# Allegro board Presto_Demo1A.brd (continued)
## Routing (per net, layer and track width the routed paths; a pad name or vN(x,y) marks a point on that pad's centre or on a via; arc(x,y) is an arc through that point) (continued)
DDR_DQ26: length 19.8
  TOP w0.102: U2.L4 v1(54.25,93.15) ; U13.D7 v1(41.5,90.3)
  INNER1 w0.102: v1(41.5,90.3) 42.06,90.86 42.61,90.86 43.36,91.61 43.9,91.61 44,91.72 44,91.82 44.1,91.92 44.31,91.92 44.41,91.82 44.41,91.72 44.51,91.61 44.72,91.61 44.82,91.72 44.82,91.82 44.92,91.92 45.12,91.92 45.23,91.82 45.23,91.72 45.33,91.61 45.88,91.61 46.49,92.23 47.05,92.23 47.16,92.13 47.16,91.72 47.26,91.61 47.46,91.61 47.56,91.72 47.56,92.13 47.67,92.23 48.28,92.23 48.5,92.45 49.46,92.45 49.55,92.54 49.55,92.96 49.64,93.05 49.78,93.05 49.87,92.96 49.87,92.54 49.96,92.45 50.1,92.45 50.21,92.55 50.21,92.97 50.31,93.07 50.45,93.07 50.55,92.97 50.55,92.7 50.7,92.55 50.84,92.55 51.02,92.73 51.17,92.73 51.26,92.82 51.26,93.26 51.35,93.35 51.48,93.35 51.56,93.26 51.56,92.82 51.65,92.73 53.83,92.73 v1(54.25,93.15)
DDR_DQ27: length 19.9
  TOP w0.102: U2.K3 v1(53.25,94.15) ; U13.D3 v1(41.5,94.3)
  INNER1 w0.1: 46.18,94.5 45.95,94.5 45.1,93.65 44.22,93.65 44.14,93.74 44.14,93.81 44.05,93.9 43.92,93.9 43.84,93.81 43.84,93.74 43.75,93.65 43.62,93.65 43.54,93.74 43.54,93.81 43.45,93.9 43.33,93.9 43.24,93.81 43.24,93.74 43.15,93.65 43.02,93.65 42.94,93.74 42.94,93.81 42.85,93.9 42.72,93.9 42.64,93.81 42.64,93.74 42.55,93.65 42.15,93.65 v1(41.5,94.3)
  INNER1 w0.102: 46.18,94.5 46.39,94.5 46.49,94.6 46.49,94.81 46.59,94.91 46.79,94.91 46.9,94.81 46.9,94.6 47,94.5 47.14,94.5 47.24,94.6 47.24,94.81 47.35,94.91 47.49,94.91 47.59,94.81 47.59,93.8 47.7,93.7 48.14,93.7 48.24,93.8 48.24,94.6 48.34,94.7 48.49,94.7 48.69,94.5 48.83,94.5 48.94,94.6 48.94,94.81 49.04,94.91 49.24,94.91 49.34,94.81 49.34,94.6 49.45,94.5 49.65,94.5 49.75,94.6 49.75,94.81 49.85,94.91 50.06,94.91 50.16,94.81 50.16,94.6 50.26,94.5 50.8,94.5 51.02,94.71 51.36,94.71 51.45,94.8 51.45,95.21 51.54,95.3 51.66,95.3 51.75,95.21 51.75,94.8 51.84,94.71 52.29,94.71 52.85,94.15 v1(53.25,94.15)
DDR_DQ28: length 20.3
  TOP w0.102: U13.D1 v1(41.5,95.9) ; U2.H4 v1(54.25,97.15)
  INNER1 w0.102: v1(54.25,97.15) 53.79,96.69 52.89,96.69 52.58,96.38 50.88,96.38 50.81,96.45 49.84,96.45 49.31,96.98 48.99,96.98 48.77,96.76 48.2,96.76 48.1,96.86 48.1,96.96 48,97.06 47.8,97.06 47.7,96.96 47.7,96.86 47.59,96.76 47.03,96.76 46.81,96.98 45.95,96.98 45.85,97.08 45.85,97.19 45.74,97.29 45.54,97.29 45.44,97.19 45.44,97 45.34,96.9 45.13,96.9 45.03,97 45.03,97.19 44.93,97.29 44.72,97.29 44.62,97.19 44.62,97 44.52,96.9 44.32,96.9 44.21,97 44.21,97.19 44.11,97.29 43.91,97.29 43.81,97.19 43.81,97 43.7,96.9 43.5,96.9 43.4,97 43.4,97.15 43.3,97.25 43.02,97.25 42.78,97.01 42.05,97.01 41.98,96.93 41.98,96.83 42.05,96.76 42.65,96.76 42.75,96.65 42.75,96.45 42.65,96.35 42.41,96.35 42.3,96.46 41.94,96.46 41.61,96.79 41.49,96.79 41.39,96.69 41.39,96.56 41.71,96.24 41.71,96.11 v1(41.5,95.9)
DDR_DQ29: length 20.3
  TOP w0.102: U13.D9 v1(41.5,88.7) ; U2.N3 v1(53.25,91.15)
  INNER1 w0.102: v1(41.5,88.7) 41.88,89.08 43.23,89.08 43.52,89.37 43.52,89.66 43.78,89.92 44.06,89.92 44.34,90.2 44.59,90.2 44.69,90.1 44.69,89.4 44.79,89.3 44.99,89.3 45.1,89.4 45.1,90.1 45.2,90.2 45.4,90.2 45.5,90.1 45.5,89.4 45.61,89.3 45.81,89.3 45.91,89.4 45.91,90.1 46.02,90.2 47.22,90.2 47.32,90.1 47.32,89.45 47.42,89.35 47.57,89.35 47.67,89.45 47.67,90.1 47.77,90.2 48.08,90.2 48.17,90.11 48.17,89.44 48.26,89.35 48.39,89.35 48.47,89.44 48.47,90.11 48.56,90.2 48.91,90.2 49,90.29 49,90.38 49.09,90.47 50.77,90.47 51.02,90.71 52.81,90.71 v1(53.25,91.15)
DDR_DQ30: length 19.8
  TOP w0.102: U13.B1 v1(43.1,95.9) ; U2.J4 v1(54.25,95.15)
  INNER1 w0.1: 45.6,96.21 45.46,96.35 44.85,96.35 44.76,96.26 44.76,95.44 44.67,95.35 44.55,95.35 44.46,95.44 44.46,96.26 44.37,96.35 43.55,96.35 v1(43.1,95.9)
  INNER1 w0.102: v1(54.25,95.15) 53.69,95.71 53.48,95.71 53.38,95.81 53.38,96.22 53.28,96.33 53.08,96.33 52.97,96.22 52.97,95.81 52.87,95.71 52.67,95.71 52.37,96.02 51.59,96.02 51.36,95.78 50.66,95.78 50.55,95.88 50.55,95.99 50.45,96.09 50.25,96.09 50.14,95.99 50.14,95.88 50.04,95.78 49.83,95.78 49.36,95.31 49.05,95.31 48.58,95.78 48.23,95.78 48.13,95.88 48.13,96.29 48.03,96.39 47.82,96.39 47.72,96.29 47.72,95.88 47.62,95.78 47.27,95.78 46.8,95.31 46.5,95.31 46.05,95.76 45.92,95.76 45.4,95.24 45.27,95.24 45.18,95.33 45.18,95.45 45.71,95.98 45.71,96.1 45.6,96.21
DDR_DQ31: length 20.8
  TOP w0.102: U2.N4 v1(54.25,91.15) ; U13.B9 v1(43.1,88.7)
  INNER1 w0.102: v1(54.25,91.15) 53.63,90.53 51.09,90.53 50.81,90.25 50.48,90.25 50.37,90.15 50.37,88.15 50.27,88.05 50.07,88.05 49.97,88.15 49.97,89.05 49.77,89.25 48.85,89.25 48.68,89.08 48.54,89.08 48.45,88.99 48.45,88.54 48.37,88.45 48.24,88.45 48.15,88.54 48.15,88.99 48.06,89.08 47.94,89.08 47.85,88.99 47.85,88.54 47.76,88.45 47.64,88.45 47.55,88.54 47.55,88.99 47.46,89.08 45.65,89.08 45.57,88.99 45.57,88.44 45.48,88.35 45.35,88.35 45.26,88.44 45.26,88.99 45.18,89.08 45.05,89.08 44.96,88.99 44.96,88.44 44.87,88.35 44.75,88.35 44.66,88.44 44.66,88.99 44.57,89.08 43.63,89.08 43.25,88.7 v1(43.1,88.7)
DDR_LDM1: length 48.7
  TOP w0.102: U12.F3 v1(39.9,108.1) ; U2.P6 v1(56.25,90.15)
  INNER1 w0.102: v1(56.25,90.15) 55.85,90.55 54.71,90.55 51.66,87.5 38.45,87.5 37.66,88.29 37.66,90.84 37.26,91.25 37.26,94.65 37.07,94.84 37.07,96.92 37.66,97.52 37.66,100.75 37.33,101.08 37.33,104.33 37.8,104.8 37.8,109.85 38.05,110.1 40.1,110.1 40.32,109.88 40.32,108.52 v1(39.9,108.1)
DDR_LDM2: length 19.5
  TOP w0.102: U13.F3 v1(39.9,94.3) ; U2.N6 v1(56.25,91.15)
  INNER2 w0.102: v1(56.25,91.15) 55.87,91.53 53.42,91.53 52.4,92.55 51.65,92.55 51.45,92.75 51,92.75 49.4,94.35 45.45,94.35 44.75,93.65 40.55,93.65 v1(39.9,94.3)
DDR_LDQS1: length 41.9
  TOP w0.102: U2.M6 v1(56.25,92.15) ; U12.F7 v1(39.9,104.1)
  INNER1 w0.102: v1(39.9,104.1) 39.45,104.55 37.85,104.55 37.51,104.21 37.51,101.2 38.08,100.63 38.26,100.63 38.5,100.39 38.5,97.45 37.9,96.85 37.9,93.8 37.45,93.34 37.45,91.32 37.85,90.92 37.85,88.4 38.55,87.7 51.6,87.7 54.65,90.75 55.6,90.75 55.8,90.95 55.8,91.7 v1(56.25,92.15)
DDR_LDQS2: length 20.3
  TOP w0.102: U2.T6 v1(56.25,88.15) ; U13.F7 v1(39.9,90.3)
  INNER2 w0.102: v1(56.25,88.15) 55.79,88.15 55.41,88.53 53.09,88.53 52.06,87.5 41.1,87.5 40.28,88.32 40.28,89.92 v1(39.9,90.3)
DDR_ODT1: length 42.1
  TOP w0.102: U2.T7 v1(57.25,88.15) ; U12.K9 v1(35.9,102.5)
  INNER1 w0.102: v1(57.25,88.15) 57.25,86.9 56.55,86.2 56.55,85.85 56.3,85.6 53.55,85.6 52.85,86.3 35.6,86.3 34.9,87 34.9,88.4 35.52,89.02 35.52,100.67 35.9,101.05 v1(35.9,102.5)
DDR_ODT2: length 26.4
  TOP w0.102: U13.K9 v1(35.9,88.7) ; U2.R7 v1(57.25,89.15)
  INNER1 w0.102: v1(57.25,89.15) 57.25,89.1 56.7,88.55 56.7,87.23 55.97,86.5 36.57,86.5 36.02,87.05 36.02,87.13 35.85,87.3 35.85,88.65 v1(35.9,88.7)
DDR_RAS: length 45.7
  TOP w0.1: U2.P7 57.75,90.15 58.1,89.8 58.1,88.22 57.45,87.57 46.99,87.57 46.09,88.47 46.09,89.21 44.05,91.25 36.9,91.25 36.35,90.7 U13.K7
  TOP w0.102: U12.K7 v1(35.9,104.1) ; v1(35.9,90.3) U13.K7
  INNER2 w0.102: v1(35.9,90.3) 35.9,90.55 36.3,90.95 36.3,93.2 37.1,94 37.1,94.5 36.46,95.14 36.46,96.39 36.15,96.7 34.55,96.7 34.1,97.15 34.1,101.15 35.45,102.5 35.45,102.65 35.7,102.9 36.08,102.9 36.28,103.1 36.28,103.72 v1(35.9,104.1)
DDR_UDM1: length 29.6
  TOP w0.102: U12.B3 v1(43.1,108.1) ; U2.M7 v1(57.25,92.15)
  INNER2 w0.102: v1(57.25,92.15) 57.85,92.75 57.85,93.35 57.47,93.73 56.2,93.73 55.88,94.05 55.88,94.37 55.52,94.73 54.13,94.73 53.83,95.03 53.83,95.38 53.16,96.05 52.55,96.05 52.01,96.59 52.01,96.6 51.81,96.8 51.81,101.49 51.55,101.75 51,101.75 50.87,101.62 44.83,101.62 44.65,101.8 44.65,105.9 44.05,106.5 44.05,107.15 v1(43.1,108.1)
DDR_UDM2: length 16.7
  TOP w0.102: U2.L7 v1(57.25,93.15) ; U13.B3 v1(43.1,94.3)
  INNER2 w0.102: v1(43.1,94.3) 43.5,93.9 44.4,93.9 45.03,94.53 49.51,94.53 50.22,93.82 50.23,93.82 51.1,92.95 51.55,92.95 51.73,92.77 56.41,92.77 56.79,93.15 v1(57.25,93.15)
DDR_UDQS1_N: length 29.6
  TOP w0.102: v1(59.25,89.95) 59.25,89.15 U2.T9 ; U12.A8 v1(43.9,103.3)
  INNER2 w0.102: v1(59.25,89.95) 58.95,90.25 58.95,91.05 58.35,91.65 57,91.65 56.75,91.9 56.75,92.45 57,92.7 57.4,92.7 57.63,92.93 57.63,93.31 57.39,93.55 56.1,93.55 55.7,93.95 55.7,94.25 55.4,94.55 54.05,94.55 53.65,94.95 53.65,95.3 53.1,95.85 52.45,95.85 51.63,96.67 51.63,101.37 51.45,101.55 51.1,101.55 50.95,101.4 44.75,101.4 44.45,101.7 44.45,102.75 v1(43.9,103.3)
DDR_UDQS1_P: length 32.3
  TOP w0.1: U12.B7 43.45,105.25 50.83,105.25 ; 59.23,104.67 59.3,104.6 59.3,90.55 59.75,90.1 U2.R9
  TOP w0.2: 50.83,105.25 58.65,105.25 59.23,104.67
DDR_UDQS2_N: length 19.3
  TOP w0.102: U13.B7 v1(43.1,90.3) ; U2.P9 v1(60.25,90.15)
  INNER2 w0.1: v1(60.25,90.15) 59.65,89.55 50.15,89.55 49.5,90.2
  INNER2 w0.102: v1(43.1,90.3) 43.48,90.68 44.06,90.68 44.54,90.2 49.5,90.2
DDR_UDQS2_P: length 21.8
  TOP w0.102: U13.A8 v1(43.9,89.5) ; U2.N9 v1(60.25,91.15)
  INNER2 w0.102: v1(60.25,91.15) 60.25,91.1 60.65,90.7 60.65,89.95 60.05,89.35 59.1,89.35 58.5,88.75 53,88.75 51.93,87.68 44.42,87.68 44.28,87.82 44.28,89.12 v1(43.9,89.5)
DDR_WE: length 45.6
  TOP w0.102: U13.K3 v1(35.9,94.3) ; U2.P8 v1(58.25,91.15) ; U12.K3 v1(35.9,108.1)
  INNER2 w0.102: v1(35.9,94.3) 35.9,95.2 35.5,95.6 35.5,96.18 35.4,96.28 34.33,96.28 33.68,96.93 33.68,101.3 34.88,102.5 34.88,102.98 34.72,103.14 34.72,104.58 33.9,105.4 33.9,108.25 34.15,108.5 35.5,108.5 v1(35.9,108.1)
  BOTTOM w0.102: v1(35.9,94.3) 35.9,92.55 37.15,91.3 47.04,91.3 47.05,91.31 48.75,91.31 48.76,91.3 49.6,91.3 50.07,91.77 51.65,91.77 51.87,91.55 57.85,91.55 v1(58.25,91.15)
DDS.DATA0: length 21.4
  TOP w0.102: U2.B10 v1(61.25,103.15)
  TOP w0.2: v2(71.8,113.85) 72.5,113.16 U4.4
  INNER1 w0.102: 61.49,104.67 61.25,104.43 v1(61.25,103.15)
  INNER1 w0.2: 61.49,104.67 62.22,105.4 63.28,105.4 64.75,106.87 64.75,111.55 66.75,113.55 71.5,113.55 v2(71.8,113.85)
DDS.DATA1: length 24
  TOP w0.102: U2.C10 v1(61.25,102.15)
  TOP w0.2: U4.3 v2(75.1,113.81)
  INNER1 w0.102: 63.72,104.67 62.75,103.7 61.95,103.7 61.8,103.55 61.8,102.7 v1(61.25,102.15)
  INNER1 w0.2: v2(75.1,113.81) 74.41,113.81 73.36,112.75 67.12,112.75 65.55,111.18 65.55,106.53 63.72,104.7 63.72,104.67
DDS.DATA2: length 25
  TOP w0.102: U2.E10 v1(61.25,100.15)
  TOP w0.2: v2(72.32,114.47) 72.34,114.46 U4.2
  INNER1 w0.102: 60.92,104.67 60.87,104.62 60.87,100.53 v1(61.25,100.15)
  INNER1 w0.2: v2(72.32,114.47) 72.32,114.47 72.3,114.46 71.55,114.46 71.54,114.45 71.35,114.45 70.85,113.95 66.58,113.95 64.35,111.72 64.35,107.03 63.12,105.8 62.05,105.8 60.92,104.67
DDS.DATA3: length 29.7
  TOP w0.102: U2.F10 v1(61.25,99.15)
  TOP w0.2: U4.1 v2(75.1,115.11)
  INNER1 w0.102: v1(61.25,99.15) 61.25,99.6 60.69,100.16 60.69,103.71 60.5,103.9 60.5,104.67
  INNER1 w0.2: 60.5,104.67 60.5,104.9 61.4,105.8 61.48,105.8 61.88,106.2 62.95,106.2 63.95,107.2 63.95,111.88 66.42,114.35 70.65,114.35 71.41,115.11 v2(75.1,115.11)
DDS.DATA4: length 34.5
  TOP w0.102: U2.E11 v1(62.25,100.15)
  TOP w0.2: U4.28 v2(82.3,115.11)
  INNER2 w0.1: 66.98,103.34 67.63,103.99 67.63,104.67
  INNER2 w0.102: v1(62.25,100.15) 62.6,100.5 64.6,100.5 65.93,101.83 65.93,103.11 66.16,103.34 66.98,103.34
  INNER2 w0.2: v2(82.3,115.11) 81.05,113.85 78.05,113.85 76.8,112.6 76.8,111.73 76.8,111.4 76.8,111.4 76.8,111.39 75.62,110.2 74.69,110.2 72.94,111.95 70.05,111.95 69,110.9 69,106.47 67.63,105.1 67.63,104.67
DDS.DATA5: length 31.5
  TOP w0.102: U2.D11 v1(62.25,101.15)
  TOP w0.2: U4.27 v2(79.54,114.46)
  INNER2 w0.1: 67.05,104.67 67.05,104.49 66.83,104.27 66.83,103.77 66.58,103.52 66.08,103.52 65.75,103.18 65.75,101.9
  INNER2 w0.102: v1(62.25,101.15) 62.7,100.7 64.54,100.7 65.75,101.9
  INNER2 w0.2: 67.05,104.67 67.05,105.08 68.6,106.63 68.6,111.11 69.84,112.35 73.1,112.35 74.85,110.6 75.45,110.6 76.4,111.55 76.4,112.77 77.88,114.25 77.9,114.25 78.15,114.5 79.5,114.5 v2(79.54,114.46)
DDS.DATA6: length 30.5
  TOP w0.102: U2.C11 v1(62.25,102.15)
  TOP w0.2: U4.26 v2(82.3,113.81)
  INNER1 w0.102: v1(62.25,102.15) 62.3,102.15 62.7,102.55 62.7,103.2 64.17,104.67 64.25,104.67
  INNER1 w0.2: 64.25,104.67 65.95,106.37 65.95,110.9 67.4,112.35 73.53,112.35 74.38,113.2 77.45,113.2 78.1,112.55 79.8,112.55 81.05,113.8 82.3,113.8 v2(82.3,113.81)
DDS.DATA7: length 27.3
  TOP w0.102: U2.A11 v1(62.25,104.15)
  TOP w0.2: U4.25 v2(79.54,113.16)
  INNER1 w0.102: 62.25,104.67 v1(62.25,104.15)
  INNER1 w0.2: v2(79.54,113.16) 78.14,113.16 76.89,114.41 74.45,114.41 73.19,113.15 66.95,113.15 65.15,111.35 65.15,106.7 63.45,105 62.45,105 62.25,104.8 62.25,104.67
DDS.FQUD: length 18
  TOP w0.102: U2.B12 v1(63.25,103.15)
  TOP w0.2: U4.8 v2(72.34,110.56)
  INNER1 w0.102: v1(63.25,103.15) 63.7,103.6 65.45,103.6 65.75,103.9 65.75,104.67
  INNER1 w0.2: v2(72.34,110.56) 72.34,110.55 71.3,110.55 70.66,111.19 67.46,111.19 66.75,110.48 66.75,106.04 65.75,105.04 65.75,104.67
DDS.RESET: length 26.4
  TOP w0.102: U2.A13 v1(64.25,104.15)
  TOP w0.2: U4.22 v2(82.3,111.21)
  INNER1 w0.102: v1(64.25,104.15) 64.77,104.67 64.82,104.67
  INNER1 w0.2: 64.82,104.67 66.35,106.2 66.35,110.65 67.6,111.9 71.74,111.9 71.75,111.91 72.25,111.91 72.26,111.9 78.55,111.9 78.75,112.1 81.41,112.1 v2(82.3,111.21)
DDS.WCLK: length 20
  TOP w0.102: U2.A14 v1(65.25,104.15)
  TOP w0.2: U4.7 v2(75.1,111.21)
  INNER2 w0.1: 66.5,103.7 66.65,103.85 66.65,104.47
  INNER2 w0.102: v1(65.25,104.15) 65.25,104.1 65.65,103.7 66.5,103.7
  INNER2 w0.2: 66.65,104.47 66.65,105.25 68.2,106.8 68.2,111.3 69.65,112.75 73.56,112.75 v2(75.1,111.21)
DDS_CLK: length 64.2
  TOP w0.2: v2(71.7,109.9) 73.72,109.9 U4.9
  INNER1 w0.2: v2(71.7,109.9) 72.9,109.9 74.63,108.17 74.63,85.64 73.1,84.1 73.1,81.95 71.05,79.9 65.3,79.9 64.6,79.2 64.6,76.1 62.05,73.55 49.79,73.55 L4.2
DDS_OUT: length 41.7
  TOP w0.2: U4.20 v2(82.3,109.91)
  TOP w0.5: v2(103.6,123) 103.6,124.18 L5.1 106.33,124.22 C34.2 108.2,124.57 C36.2
  BOTTOM w0.5: v2(103.6,123) 103.6,111.5 102,109.91 v2(82.3,109.91)
DEN/: length 66.5
  TOP w0.2: v2(26.85,139.85) 25.65,139.85 U6.48 ; v2(26.75,106.09) 26.79,106.05 ; 26.79,106.05 25.54,106.05 U9.48 ; 26.79,106.05 28.22,106.05 28.68,105.59 28.68,85.38 27.37,84.07 U7.17
  BOTTOM w0.2: v2(26.75,106.09) 26.75,111.02 25.1,112.66 25.1,119.3 24.41,120 22.67,120 22.32,120.35 22.32,135.32 v2(26.85,139.85)
DHEN/: length 33.1
  TOP w0.2: v2(27.45,85.1) 27.21,85.34 26.04,85.34 ; v2(27.15,112.65) 27.15,112.65 27.15,112.3 26.67,111.82 26.67,111.82 26.49,111.64 26.49,111.64 26.45,111.6 25.65,111.6 U8.25
  INNER2 w0.2: v2(27.15,112.65) 29.6,110.2 29.6,87.25 v2(27.45,85.1)
DI: length 63.2
  TOP w0.102: U1.C12 v1(42.9,121.2)
  INNER1 w0.102: v1(42.9,121.2) 42.95,121.15 42.95,118.74
  INNER1 w0.2: P1.7 42.68,82.82 41.65,83.85 29.95,83.85 29.5,84.3 29.5,108.18 34.32,113 42,113 42.95,113.95 42.95,118.74
DIFF1+: length 47.1
  TOP w0.102: U1.D16 v1(38.9,122.2)
  TOP w0.127: U6.5 19,137.86 19.12,137.73 19.57,137.73 21.1,136.2 21.1,133.96 22.6,132.45 22.6,123.16 23.55,122.21 23.55,121.38 23.55,121.37 23.55,121.25 v2(23.83,120.97) 23.65,120.79 23.65,117.66 19.71,113.72 19.12,113.72 19,113.59 U8.20
  INNER2 w0.102: 38.32,122.2 v1(38.9,122.2)
  INNER2 w0.127: v2(23.83,120.97) 24.03,121.17 26.08,121.17 27.11,122.2 38.32,122.2
DIFF1-: length 50.2
  TOP w0.102: U1.D14 v1(40.9,122.2)
  TOP w0.127: U6.6 19,137.36 19.12,137.48 19.46,137.48 20.85,136.09 20.85,133.85 22.35,132.35 22.35,123.05 23.3,122.1 23.3,121.48 23.3,121.25 v2(23.02,120.97) 23.03,120.97 23.4,120.6 23.4,117.76 19.6,113.97 19.12,113.97 19,114.09 U8.19
  INNER2 w0.102: v1(40.9,122.2) 40.45,121.75 39.45,121.75 39.28,121.92 39.28,122.36 39.06,122.58 38.32,122.58
  INNER2 w0.127: 38.32,122.58 38.19,122.45 27,122.45 25.97,121.42 24.18,121.42 24.07,121.54 23.59,121.54 23.48,121.42 23.47,121.42 v2(23.02,120.97)
DQ0: length 4.1
  TOP w0.2: 82.73,51.35 82.73,51.35 U38.12
DQ1: length 4.1
  TOP w0.2: U38.13 82.73,52.62 82.73,52.62
DQ2: length 4.1
  TOP w0.2: 82.73,53.89 78.6,53.89 U38.14
DQ3: length 4.1
  TOP w0.2: U38.15 78.6,55.16 82.73,55.16
DQ4: length 4.1
  TOP w0.2: 82.73,56.43 82.73,56.43 U38.16
DQ5: length 4.1
  TOP w0.2: U38.17 78.6,57.7 82.73,57.7
DQ6: length 4.1
  TOP w0.2: U38.18 82.73,58.97 82.73,58.97
DQ7: length 4.1
  TOP w0.2: 82.73,60.24 78.6,60.24 U38.19
DQ8: length 4.1
  TOP w0.2: 82.73,66.83 82.73,66.83 U39.12
DQ9: length 4.1
  TOP w0.2: U39.13 78.6,68.1 82.73,68.1
DQ10: length 4.1
  TOP w0.2: 82.73,69.37 82.73,69.37 U39.14
DQ11: length 4.1
  TOP w0.2: U39.15 78.6,70.64 82.73,70.64
DQ12: length 4.1
  TOP w0.2: 82.73,71.91 82.73,71.91 U39.16
DQ13: length 4.1
  TOP w0.2: 82.73,73.18 78.6,73.18 U39.17
DQ14: length 4.1
  TOP w0.2: U39.18 82.73,74.45 82.73,74.45
DQ15: length 4.1
  TOP w0.2: U39.19 78.6,75.72 82.73,75.72
E: length 178.5
  TOP w0.1: U1.C1 v1(54.88,122.18)
  INNER1 w0.1: 38.32,129.09 38.8,128.6 40.95,128.6 42.7,126.85 45.95,126.85 46.57,126.23 46.57,124.08 47.95,122.7 52.65,122.7 53.51,121.84 54.54,121.84 v1(54.88,122.18)
  INNER1 w0.2: 38.32,129.09 33.61,129.09 33.45,129.25 33.43,129.25 27.7,134.98 27.7,149.65 31.05,153 31.05,157.8 35.45,162.2 52.3,162.2 52.9,162.8 52.9,164.05
  INNER1 w0.4: 52.9,164.05 52.9,207.2 ; 93.1,215.6 83.95,215.6 82.91,216.64 57.44,216.64 56.4,215.6 51.6,215.6
  INNER2 w0.4: 52.9,207.2 52.9,214.3 51.6,215.6
FPGA/: length 21.8
  TOP w0.2: U48.5 16.64,67.55 19.35,67.55 21.3,69.5 21.3,80.7 22.13,81.53 U7.15
GAIN: length 124
  TOP w0.102: U1.J4 v1(51.9,128.2)
  TOP w0.2: 95.45,75.42 95.49,75.45 v2(97.3,75.45) 97.9,76.05 97.9,80.1 v2(97.85,80.15) ; v2(97.4,60.3) 97.04,59.94 95.45,59.94
  INNER1 w0.102: 55.59,127.95 55.42,127.95 55.27,127.8 52.3,127.8 v1(51.9,128.2)
  INNER1 w0.2: v2(97.4,60.3) 97.1,60.3 96.15,61.25 96.15,74.3 v2(97.3,75.45) ; v2(97.85,80.15) 97.95,80.05 102.1,80.05 103.85,81.81 103.85,84.09 103.25,84.7 103.25,93.56 102.59,94.23 100.9,95.92 100.9,105.84 101.81,106.74 101.81,116.06 97.37,120.5 75.37,120.5 71.3,124.57 71.3,125.14 69.59,126.85 63.66,126.85 63.62,126.8 62.78,126.8 62.73,126.85 60.42,126.85 59.32,127.95 55.59,127.95
HS/: length 21.6
  TOP w0.2: U48.4 19.33,68.83 20.9,70.4 20.9,81.35 22.35,82.8 U7.16
JTAG_D0: length 43.7
  TOP w0.102: U2.E14 v1(65.25,100.15)
  BOTTOM w0.1: 61.87,87.5 60.85,88.52
  BOTTOM w0.102: 60.85,88.52 60.85,91.4 61,91.55 61.6,91.55 61.87,91.82 61.87,92.42 62.25,92.8 64.35,92.8 65.05,93.5 65.05,97.67 65.35,97.97 65.35,100.05 v1(65.25,100.15)
  BOTTOM w0.2: P1.8 43.97,79.85 48.15,79.85 49,80.7 49,81.85 49.58,82.43 57.22,82.43 57.65,82.86 59.91,82.86 60.85,83.8 61.87,83.8 62.75,84.68 62.75,86.28 62.75,86.28 62.75,86.62 61.87,87.5
LED1: length 1.7
  TOP w0.2: Q4.1 117.65,101.86 117.64,101.85 R31.2
LED2: length 1.7
  TOP w0.2: R32.2 117.64,95.72 117.65,95.73 Q5.1
LED3: length 1.7
  TOP w0.2: Q6.1 117.65,89.6 117.64,89.59 R33.2
LED4: length 1.7
  TOP w0.2: Q7.1 117.65,83.47 117.64,83.46 R34.2
LPF_OUT: length 4.7
  TOP w0.5: R17.2 94.47,124.92 C42.1 91.97,124.92 R18.2
MEMORY.CTRL.RCS0: length 85.2
  TOP w0.102: U1.J1 v1(53.9,128.2)
  TOP w0.2: U40.22 38.21,149.23 v2(36.22,149.23) ; U44.22 v2(80.25,149.22)
  INNER2 w0.2: v2(80.25,149.22) 75.07,149.22 73.1,147.25 58.35,147.25 57,148.59 50,148.59 49.38,149.23 v2(36.22,149.23)
  BOTTOM w0.1: v1(53.9,128.2) 53.9,128.75 52.83,129.82 52.83,129.82 52.72,129.93 52.72,130.88 51.77,131.82 50.74,131.82 50.52,132.04 50.52,133.36 50.65,133.49 50.65,136.01
  BOTTOM w0.2: v2(36.22,149.23) 36.25,149.2 42.1,149.2 42.85,148.45 J7.26 42.85,139.8 43.75,138.9 48.5,138.9 50.65,136.75 50.65,136.01
MEMORY.CTRL.RCS1: length 82.4
  TOP w0.102: U1.G3 v1(52.9,125.2)
  TOP w0.2: U45.22 v2(91.05,149.22) ; U41.22 50.72,149.22 v2(50.75,149.25)
  INNER2 w0.2: v2(91.05,149.22) 89.25,151.03 82.39,151.03 81.67,150.3 79.65,150.3 79.45,150.1 74.65,150.1 74.35,149.8 70.2,149.8 69.53,150.47 64.56,150.47 v2(62.1,148) 58.5,148 57.25,149.25 v2(50.75,149.25)
  BOTTOM w0.1: 51.3,136.01 51.3,135.25 51,134.95 51,133.75 51.3,133.45 51.3,132.55 52.9,130.95 52.9,130 52.92,130 54.2,128.73 54.3,128.63 54.3,127.6 52.9,126.2 v1(52.9,125.2)
  BOTTOM w0.2: v2(62.1,148) 62.07,148.03 61.78,148.03 61.45,147.7 J7.76 61.45,145.05 61.7,144.8 62,144.8 62.35,144.45 62.35,143.05 61.7,142.4 61.7,141.35 59.95,139.6 52.4,139.6 51.3,138.5 51.3,136.01
MEMORY.CTRL.RCS2: length 109.1
  TOP w0.102: U1.F2 v1(53.9,124.2)
  TOP w0.2: U46.22 v2(101.97,149.22) ; U42.22 60.02,149.2 v2(58.2,149.2)
  INNER2 w0.2: v2(101.97,149.22) 91.93,149.22 89.7,151.45 88.55,151.45 87.6,152.4 83.2,152.4 81.5,150.7 v2(77.65,150.7) 74.6,150.7 74.1,150.2 70.5,150.2 69.95,150.75 69.95,152.2 69.6,152.55 69,152.55 68.6,152.15 68.6,151.25 68.25,150.9 64.35,150.9 62.05,148.6 58.8,148.6 v2(58.2,149.2)
  BOTTOM w0.1: v1(53.9,124.2) 53.9,124.25 53.28,124.87 53.28,126.28 54.5,127.5 54.5,128.68 53.08,130.1 53.08,131.07 51.5,132.65 51.5,133.55 51.2,133.85 51.2,134.85 51.7,135.35 51.7,136.01
  BOTTOM w0.2: v2(77.65,150.7) 77.65,147.75 77.4,147.5 76.65,147.5 76.45,147.3 J7.126 76.45,145.11 76.73,144.82 77.24,144.82 77.5,144.56 77.5,142.1 73.95,138.55 70.35,138.55 69.75,139.15 52.6,139.15 51.7,138.25 51.7,136.01
MEMORY.CTRL.RCS3: length 124.5
  TOP w0.102: U1.G6 v1(49.9,125.2)
  TOP w0.2: U43.22 70.94,149.2 v2(69.1,149.2) ; U47.22 v2(112.77,149.22)
  INNER2 w0.2: v2(69.1,149.2) 74.35,149.2 74.85,149.7 79.75,149.7 79.9,149.85 82.7,149.85 83.15,149.4 84.1,149.4 85.07,150.38 v2(88.47,150.38) 89.03,150.38 90.8,148.6 102.2,148.6 102.22,148.62 102.22,148.62 102.57,148.97 102.57,148.98 102.82,149.22 v2(112.77,149.22)
  BOTTOM w0.1: v1(49.9,125.2) 50.35,124.75 52.7,124.75 53.65,123.8 54.2,123.8 54.3,123.9 54.3,124.45 54.1,124.65 53.8,124.65 53.5,124.95 53.5,126.2 54.7,127.4 54.7,128.75 53.26,130.19 53.26,131.14 51.68,132.73 51.68,133.62 51.4,133.91 51.4,134.75 52.1,135.45 52.1,136.01
  BOTTOM w0.2: 52.1,136.01 52.1,137.95 52.8,138.65 69.69,138.65 70.23,138.1 89.9,138.1 91.45,139.65 J7.176 91.45,148 90.83,148.62 90.8,148.62 89.05,150.38 v2(88.47,150.38)
MEMORY.CTRL.RWE: length 129.7
  TOP w0.102: U1.M11 v1(43.9,131.2)
  TOP w0.2: U40.29 38.23,158.09 39.69,158.09 40.35,158.75 43.19,158.75 43.38,158.95 45.35,158.95 v2(46.15,158.15) 46.19,158.11 U41.29 49.15,158.09 50.74,158.09 51.39,158.74 54.13,158.74 54.35,158.95 55.6,158.95 56.15,158.4 58.48,158.4 58.53,158.35 59.8,158.35 U42.29 60.06,158.09 v2(61.66,158.09) 62.32,158.75 69.2,158.75 69.84,158.11 U43.29 70.97,158.09 72.57,158.09 73.22,158.74 76.56,158.74 77,158.3 v2(77.45,158.3) 80.15,158.3 80.35,158.1 81.86,158.1 U44.29 81.89,158.09 83.49,158.09 84.13,158.74 88.16,158.74 89.25,157.65 90.6,157.65 v2(91.05,158.1) 92.77,158.1 U45.29 92.8,158.09 93.94,158.09 94.59,158.74 100.12,158.74 100.74,158.11 U46.29 105.28,158.11 105.91,158.74 110.77,158.74 111.39,158.11 U47.29
  INNER1 w0.102: 45.68,136.01 45.46,135.79 45.46,133.22 45.06,132.82 44.74,132.82 44.28,132.36 44.28,132.04 43.9,131.66 v1(43.9,131.2)
  INNER1 w0.2: 45.68,136.01 45.68,139.98 47.2,141.5 47.2,149.5 45.15,151.55 45.15,157.15 v2(46.15,158.15)
  BOTTOM w0.2: v2(46.15,158.15) 43.95,158.15 43.15,157.35 J7.27 ; v2(61.66,158.09) 61.75,158 J7.77 ; J7.127 76.75,157.6 v2(77.45,158.3) ; v2(91.05,158.1) 91.75,157.4 J7.177
MEMORY.RA0: length 131.2
  TOP w0.102: U1.P5 v1(50.9,133.2)
  TOP w0.15: 62.95,147.95 62.18,147.32 61.98,147.32
  TOP w0.2: 61.98,147.32 57.97,147.32 56.95,148.35 55.45,148.35 v2(55.05,147.95) U42.12 51.57,147.95 50.94,147.32 45.5,147.32 44.88,147.95 U41.12 40.2,147.95 39.58,147.32 34.59,147.32 34,147.92 v2(34,147.95) U40.12 ; U47.12 105.99,147.95 105.36,147.32 100.07,147.32 98.9,148.5 98.4,148.5 97.85,147.95 U46.12 95.4,147.95 94.78,147.32 90.88,147.32 89.3,148.9 87.75,148.9 86.8,147.95 U45.12 84.16,147.95 83.53,147.32 79.42,147.32 v2(78.8,147.95) 78.05,147.95 77.3,148.7 76.8,148.7 76.05,147.95 U44.12 73.24,147.95 72.62,147.32 68.53,147.32 v2(67.1,148.75) 65.95,148.75 65.15,147.95 U43.12 62.95,147.95
  INNER1 w0.102: v1(50.9,133.2) 50.9,134.25 52.11,135.46 52.11,136.01
  INNER1 w0.2: 52.11,136.01 52.11,138.56 53,139.45 53,145.9 v2(55.05,147.95)
  BOTTOM w0.2: v2(34,147.95) 34.45,148.4 34.45,152.65 34.05,153.05 34.05,153.92 34.48,154.35 J7.1 ; v2(78.8,147.95) 81.6,147.95 82.7,149.05 82.7,152.05 83.95,153.3 J7.151 ; v2(55.05,147.95) 55.05,149.85 53.95,150.95 J7.51 ; v2(67.1,148.75) 67.1,151.31 68.95,153.16 J7.101
MEMORY.RA1: length 118.3
  TOP w0.102: U1.P10 v1(44.9,133.2)
  TOP w0.2: U47.11 105.99,149.22 105.36,148.59 100.26,148.59 99.55,149.3 98.07,149.3 97.99,149.22 U46.11 94.87,149.22 94.25,148.59 90.81,148.59 89.7,149.7 87.15,149.7 86.67,149.22 U45.11 83.92,149.22 v2(83.5,148.8) 83.3,148.59 79.76,148.59 78.7,149.65 76.4,149.65 75.97,149.22 U44.11 73.24,149.22 72.62,148.59 69.44,148.59 v2(69.25,148.4) 69.05,148.4 67.5,149.95 65.7,149.95 64.97,149.22 U43.11 61.87,149.22 61.25,148.59 57.95,148.59 57.33,149.22 U42.11 51.62,149.22 51,148.6 50.29,148.6 50.29,148.59 48.01,148.59 48.01,148.6 v2(46.5,148.6) 45.53,148.6 44.91,149.22 U41.11 40.02,149.22 39.9,149.1 39.88,149.1 39.37,148.59 36.01,148.59 35.85,148.75 v2(32.85,148.75) 32.38,149.22 U40.11
  INNER1 w0.102: v1(44.9,133.2) 44.9,133.66 45.28,134.04 45.28,136.01
  INNER1 w0.2: 45.28,136.01 45.28,140.18 46.5,141.4 v2(46.5,148.6)
  BOTTOM w0.2: J7.52 54.25,147.3 53.9,147.65 53.9,148.3 53.6,148.6 v2(46.5,148.6) ; J7.2 35.16,146.15 35.09,146.08 33.87,146.08 32.85,147.1 v2(32.85,148.75) ; J7.152 84.25,148.05 v2(83.5,148.8) ; J7.102 v2(69.25,148.4)
MEMORY.RA2: length 119.8
  TOP w0.102: U1.N11 v1(43.9,132.2)
  TOP w0.2: U40.10 32.54,150.49 33.15,151.1 34.38,151.1 v2(35.62,149.87) 39.52,149.87 40.14,150.49 U41.10 44.44,150.49 v2(44.45,150.5) 45.08,149.87 50.85,149.87 51.47,150.49 U42.10 55.31,150.49 v2(55.65,150.15) 55.94,149.87 62.41,149.87 63.04,150.49 U43.10 68.03,150.49 v2(68.65,149.87) 73.27,149.87 73.89,150.49 U44.10 76.06,150.49 76.47,150.07 80.42,150.07 80.65,149.84 83.39,149.84 v2(83.75,150.2) 84.04,150.49 U45.10 87.54,150.49 88.1,151.05 89.6,151.05 90.78,149.87 94.71,149.87 95.34,150.49 U46.10 98.91,150.49 99.7,149.7 99.72,149.7 100.07,149.35 101.25,149.35 101.76,149.87 106.12,149.87 106.74,150.49 U47.10
  INNER1 w0.102: 44.46,136.01 44.46,133.22 43.9,132.66 v1(43.9,132.2)
  INNER1 w0.2: 44.46,136.01 44.45,136.03 44.45,142.15 44.76,142.45 44.76,143.28 44.45,143.59 v2(44.45,150.5)
  BOTTOM w0.2: J7.103 69.55,153.2 68.65,152.3 v2(68.65,149.87) ; J7.153 84.55,151.7 83.75,150.9 v2(83.75,150.2) ; J7.53 54.55,151.25 v2(55.65,150.15) ; J7.3 35.95,153.31 35.3,152.65 35.3,150.19 v2(35.62,149.87)
MEMORY.RA3: length 132.7
  TOP w0.102: U1.R9 v1(45.9,134.2)
  TOP w0.2: 34.02,151.75 v2(33.35,151.75) 32.75,151.75 32.74,151.76 U40.9 ; 34.02,151.75 34,151.76 ; 34.02,151.75 34.85,151.75 35.47,151.13 39.38,151.13 40.01,151.76 40.14,151.76 40.15,151.75 40.65,151.75 40.66,151.76 U41.9 44.92,151.76 45.53,151.15 v2(47,151.15) 47.95,151.15 47.97,151.13 50.98,151.13 51.61,151.76 U42.9 55.83,151.76 56.46,151.13 62.09,151.13 62.71,151.76 U43.9 68.14,151.76 68.75,151.15 v2(69.3,151.15) 69.31,151.13 72.59,151.13 73.21,151.76 U44.9 74.83,151.7 79.2,151.7 79.77,151.13 83.19,151.13 83.6,151.55 v2(83.6,151.76) U45.9 86.36,151.76 86.85,152.25 87.75,152.25 88.15,151.85 90.05,151.85 90.76,151.13 94.78,151.13 95.41,151.76 U46.9 100.94,151.76 101.56,151.13 105.69,151.13 106.31,151.76 U47.9
  INNER1 w0.102: v1(45.9,134.2) 45.9,134.66 46.48,135.24 46.48,136.01
  INNER1 w0.2: 46.48,136.01 46.48,139.58 48,141.1 48,149.9 47,150.9 v2(47,151.15)
  BOTTOM w0.2: v2(33.35,151.75) 32.75,151.15 32.75,149.85 33.45,149.15 33.45,148.5 33.35,148.4 33.35,147.65 33.65,147.35 34.55,147.35 34.67,147.48 35.96,147.48 36.14,147.3 36.14,147.3 36.25,147.19 J7.4 ; v2(47,151.15) 50.4,151.15 51.2,150.35 53.95,150.35 54.3,150 54.3,147.85 54.85,147.3 J7.54 ; v2(69.3,151.15) 69.85,150.6 J7.104 ; v2(83.6,151.76) 83.1,151.26 83.1,149.8 83.4,149.5 84.45,149.5 84.85,149.1 J7.154
MEMORY.RA4: length 117
  TOP w0.102: U1.P8 v1(47.9,133.2)
  TOP w0.2: U47.8 105.99,153.03 105.36,152.4 99.2,152.4 98.57,153.03 U46.8 95.23,153.03 94.6,152.41 88.84,152.41 v2(88.8,152.45) 88.25,152.45 87.67,153.03 U45.8 84.16,153.03 83.53,152.4 77.15,152.4 76.52,153.03 U44.8 73.68,153.03 73.25,152.6 72.34,152.6 72.15,152.41 69.7,152.41 v2(69.25,151.95) 68.6,152.6 67.16,152.6 66.71,153.05 65.55,153.05 65.53,153.03 U43.8 62.78,153.03 62.16,152.41 58.44,152.41 57.9,152.95 55.7,152.95 v2(55.4,152.65) 54.8,152.65 54.42,153.03 U42.8 51.88,153.03 51.25,152.4 v2(46.65,152.4) 46.45,152.2 43.55,152.2 42.72,153.03 U41.8 40.03,153.03 39.41,152.41 v2(35.9,152.41) 34.61,152.41 33.98,153.03 U40.8
  INNER1 w0.102: v1(47.9,133.2) 47.9,133.66 47.52,134.04 47.52,135.94 47.59,136.01
  INNER1 w0.2: v2(46.65,152.4) 46.85,152.2 47.4,152.2 48.8,150.8 48.8,137.22 47.59,136.01
  BOTTOM w0.2: J7.105 70.15,152.85 v2(69.25,151.95) ; J7.155 85.15,152 86.35,150.8 87.8,150.8 88.8,151.8 v2(88.8,152.45) ; J7.55 55.15,152.9 v2(55.4,152.65) ; v2(35.9,152.41) 36.55,153.06 J7.5
MEMORY.RA5: length 164.1
  TOP w0.102: U1.R7 v1(48.9,134.2)
  TOP w0.2: U40.7 34.02,154.3 v2(34.65,153.68) 39.47,153.68 40.1,154.3 U41.7 44.88,154.3 45.53,153.65 47.6,153.65 v2(47.65,153.7) 47.7,153.66 50.29,153.66 50.29,153.65 50.85,153.65 51.5,154.3 U42.7 55.65,154.3 56.15,153.8 58.38,153.8 58.51,153.68 62.02,153.68 62.65,154.3 U43.7 66.71,154.3 67.33,153.68 73.03,153.68 73.65,154.3 U44.7 76.55,154.3 77.18,153.68 83.53,153.68 84.16,154.3 U45.7 88.3,154.3 88.92,153.68 94.43,153.68 95.05,154.3 U46.7 96.7,154.4 99.95,154.4 100.67,153.68 105.36,153.68 105.99,154.3 U47.7
  INNER1 w0.1: 49.66,136.01 49.4,135.75 49.4,135.05 48.9,134.55 v1(48.9,134.2)
  INNER1 w0.2: v2(47.65,153.7) 48.7,153.7 50,152.4 50,148.35 50.95,147.4 v2(50.95,140.45) 50.05,139.55 50.05,139.05 50.25,138.85 50.25,136.6 49.66,136.01
  INNER2 w0.2: v2(78.65,139.4) 78.4,139.15 70.6,139.15 v2(70.4,139.35) 56.55,139.35 v2(55.45,140.45)
  BOTTOM w0.2: J7.6 36.85,148.43 36.65,148.62 35.98,148.62 34.86,149.74 34.86,152.89 34.65,153.1 v2(34.65,153.68) ; v2(70.4,139.35) 70.45,139.4 J7.106 ; v2(50.95,140.45) v2(55.45,140.45) J7.56 ; J7.156 85.45,144.61 85,144.16 85,143.55 83.75,142.3 83.75,142.05 83.15,141.45 80.7,141.45 v2(78.65,139.4)
MEMORY.RA6: length 145.7
  TOP w0.102: U1.P6 v1(49.9,133.2)
  TOP w0.2: U40.6 v2(34,155.57) 34.62,154.94 39.55,154.94 40.17,155.57 U41.6 45.23,155.57 45.86,154.94 50.79,154.94 51.42,155.57 U42.6 54.57,155.57 v2(55,156) 55.95,156 57,154.94 62.09,154.94 62.72,155.57 U43.6 66.92,155.57 67.25,155.9 v2(67.85,155.9) 68.81,154.94 72.94,154.94 73.57,155.57 U44.6 76.53,155.57 77.15,154.94 79.84,154.94 79.85,154.95 80.7,154.95 80.71,154.94 83.53,154.94 84.16,155.57 U45.6 88.23,155.57 88.86,154.94 94.25,154.94 94.85,155.55 96.58,155.55 U46.6 100.08,155.57 100.7,154.95 v2(100.85,154.95) 100.85,154.94 105.36,154.94 105.99,155.57 U47.6
  INNER1 w0.1: 51.05,136.01 51.05,135.55 50.35,134.85 50.35,133.75 49.9,133.3 v1(49.9,133.2)
  INNER1 w0.2: 51.05,136.01 51.05,138.85 51.15,138.95 51.15,138.97 52,139.81 52,140.95 51.8,141.15 51.8,154.55 53.25,156 v2(55,156) ; v2(87.95,162.05) 88.5,162.05 89,161.55 89,160.75 89.4,160.35 97.9,160.35 99.9,158.35 99.9,155.85 100.8,154.95 v2(100.85,154.95)
  BOTTOM w0.2: J7.157 85.75,161.3 86.5,162.05 v2(87.95,162.05) ; J7.107 70.75,155.45 70.5,155.7 68.05,155.7 v2(67.85,155.9) ; v2(34,155.57) 34.33,155.9 35.35,155.9 35.45,155.8 35.95,155.8 36.05,155.9 36.64,155.9 37.15,155.39 J7.7 ; v2(55,156) 55.35,156 55.75,155.6 J7.57
MEMORY.RA7: length 183.7
  TOP w0.102: U1.N5 v1(50.9,132.2)
  TOP w0.2: U47.5 105.99,156.84 105.36,156.22 100.69,156.22 100.06,156.84 U46.5 94.86,156.84 94.85,156.85 94.6,156.85 93.97,156.22 88.84,156.22 88.21,156.84 U45.5 84.16,156.84 83.53,156.22 80.73,156.22 80.37,155.85 77.45,155.85 76.46,156.84 U44.5 73.64,156.84 73.02,156.22 69.63,156.22 68.95,156.9 63.91,156.9 U43.5 62.44,156.84 61.8,156.2 58.9,156.2 58.88,156.22 57.24,156.22 56.25,157.2 54.82,157.2 54.77,157.24 v2(54.76,157.24) 54.44,157.24 54.04,156.84 U42.5 51.42,156.84 50.79,156.22 45.94,156.22 45.4,156.75 42.12,156.75 U41.5 40.24,156.84 39.61,156.22 36.83,156.22 36.05,157 35.3,157 35.14,156.84 v2(32.91,156.84) U40.5
  INNER1 w0.102: v1(50.9,132.2) 50.45,132.65 50.45,133.45 50.65,133.65 50.65,134.55 51.55,135.45
  INNER1 w0.2: v2(54.76,157.24) 55.91,157.24 56.3,156.85 56.3,155.15 55.3,154.15 52.8,154.15 52.6,153.95 52.6,141.7 52.4,141.5 v2(52.4,141.45) 52.4,139.65 51.55,138.8 51.55,135.45
  INNER2 w0.2: v2(80.15,139.95) 79.55,139.95 79.35,140.15 77,140.15 76.4,139.55 71.3,139.55 v2(71.1,139.75) 70.9,139.95 70.15,139.95 69.95,139.75 57.35,139.75 v2(56.05,141.05) 55.2,141.05 55,140.85 53.05,140.85 52.45,141.45 v2(52.4,141.45)
  BOTTOM w0.2: J7.108 71.05,139.8 v2(71.1,139.75) ; v2(80.15,139.95) 81.25,141.05 83.35,141.05 83.75,141.45 84.6,141.45 84.95,141.8 84.95,142.85 85.4,143.3 85.4,144 86.05,144.65 J7.158 ; v2(32.91,156.84) 30.75,154.68 30.75,145.6 31.7,144.65 35.85,144.65 35.95,144.75 37.09,144.75 37.45,145.11 J7.8 ; v2(56.05,141.05) 55.85,141.25 55.85,144.7 56.05,144.9 J7.58
MEMORY.RA8: length 126.2
  TOP w0.102: U1.L8 v1(47.9,130.2)
  TOP w0.2: U47.27 111.38,155.57 110.75,156.19 105.91,156.19 105.53,155.81 105.51,155.81 105.27,155.57 U46.27 100.68,155.57 100.06,156.19 94.64,156.19 93.99,155.55 92.8,155.55 U45.27 88.83,155.57 88.2,156.2 v2(87.35,156.2) 84.14,156.2 83.49,155.55 81.89,155.55 U44.27 80.75,155.57 80.63,155.45 77.25,155.45 76.5,156.2 73.6,156.2 72.95,155.55 70.97,155.55 U43.27 69.43,155.57 v2(68.7,156.3) 68.5,156.5 65.4,156.5 65.1,156.2 62.7,156.2 62.05,155.55 60.06,155.55 U42.27 57.28,155.57 56.25,156.6 v2(55.7,156.6) 54.6,156.6 54.2,156.19 51.39,156.19 50.74,155.55 49.15,155.55 U41.27 47.48,155.57 v2(47.45,155.6) 45.85,155.6 45.25,156.19 40.2,156.19 39.55,155.55 38.23,155.55 U40.27 36.83,155.57 36,156.4 v2(35.7,156.4)
  INNER1 w0.102: v1(47.9,130.2) 47.9,130.66 47.52,131.04 47.52,132.73 47.1,133.15 47.1,136.01
  INNER1 w0.2: 47.1,136.01 47.1,136.09 48.4,137.39 48.4,150.6 47.24,151.75 46.35,151.75 46.05,152.06 46.05,154.35 47.3,155.6 v2(47.45,155.6)
  BOTTOM w0.2: v2(68.7,156.3) 68.75,156.25 68.8,156.25 68.85,156.2 71.05,156.2 71.35,155.9 J7.109 ; v2(55.7,156.6) 55.7,156.55 56.35,155.9 J7.59 ; v2(87.35,156.2) 86.7,156.2 86.35,155.85 J7.159 ; J7.9 37.75,156 37.35,156.4 v2(35.7,156.4)
MEMORY.RA9: length 209.1
  TOP w0.102: U1.M6 v1(49.9,131.2)
  TOP w0.2: v2(53.6,141.45) 53,142.05 50.5,142.05 48.6,140.15 v2(38.95,140.15) ; U40.26 38.23,154.28 39.48,154.28 40.13,154.93 44.88,154.93 45.51,154.3 U41.26 49.15,154.28 50.73,154.28 51.39,154.94 54.1,154.94 54.1,154.95 56.05,154.95 56.7,154.3 U42.26 60.06,154.28 62.03,154.28 62.67,154.93 66.71,154.93 67.34,154.3 U43.26 70.97,154.28 72.88,154.28 73.55,154.94 76.56,154.94 77.2,154.3 U44.26 81.89,154.28 83.49,154.28 84.13,154.93 88.28,154.93 88.9,154.3 U45.26 92.8,154.28 94.15,154.28 94.79,154.93 100.03,154.93 100.65,154.3 U46.26 105.4,154.3 106.02,154.93 v2(110.73,154.93) 111.35,154.3 U47.26
  INNER1 w0.1: 52.76,136.01 52.76,135.66 51.5,134.4 51.5,132.15 50.55,131.2 v1(49.9,131.2)
  INNER1 w0.2: v2(110.25,141.55) 110.25,154.45 v2(110.73,154.93) ; v2(53.6,141.45) 53.6,139.4 52.76,138.56 52.76,136.01
  INNER2 w0.2: v2(53.6,141.45) 55.6,141.45 55.8,141.65 56.3,141.65 56.95,141 v2(57,141) 57.65,140.35 v2(71.65,140.35) 72.05,139.95 76.2,139.95 76.8,140.55 80.9,140.55 81,140.45 v2(81.6,140.45) 93.15,140.45 94.25,141.55 v2(110.25,141.55)
  BOTTOM w0.2: J7.110 v2(71.65,140.35) ; v2(81.6,140.45) 84.25,140.45 85.8,142 85.8,143.83 86.65,144.68 J7.160 ; v2(38.95,140.15) 37.75,140.15 37.15,140.75 37.15,144.22 37.76,144.82 37.77,144.82 38.05,145.11 J7.10 ; J7.60 56.65,144.9 56.25,144.5 56.25,141.75 v2(57,141)
MEMORY.RA10: length 115.3
  TOP w0.102: U1.T10 v1(44.9,135.2)
  TOP w0.2: v2(36.5,150.5) 38.2,150.5 U40.23 38.23,150.47 39.37,150.47 40.02,151.12 44.78,151.12 45.35,150.55 v2(45.35,150.5) 46.51,150.5 46.52,150.49 U41.23 49.15,150.47 50.89,150.47 51.53,151.12 55.8,151.12 56.41,150.5 v2(56.7,150.5) 60.03,150.5 U42.23 62.04,150.49 62.66,151.12 68.13,151.12 68.76,150.49 U43.23 72.79,150.49 v2(73.1,150.8) 73.41,151.12 76.38,151.12 76.57,151.3 78.9,151.3 79.71,150.49 U44.23 81.89,150.47 83.17,150.47 83.81,151.12 86.91,151.12 v2(87.42,151.62) 87.6,151.45 89.8,151.45 90.76,150.49 U45.23 92.8,150.47 94.72,150.47 95.37,151.12 100.84,151.12 101.45,150.5 103.69,150.5 U46.23 105.69,150.49 106.31,151.12 110.73,151.12 111.36,150.49 U47.23
  INNER1 w0.102: v1(44.9,135.2) 44.9,135.99 44.88,136.01
  INNER1 w0.2: v2(45.35,150.5) 45.25,150.4 45.25,140.75 44.88,140.38 44.88,136.01
  BOTTOM w0.2: v2(87.42,151.62) 86.95,152.1 J7.161 ; v2(36.5,150.5) 38.35,152.35 J7.11 ; v2(73.1,150.8) 73.5,151.2 73.5,152.7 73.25,152.95 72.25,152.95 71.95,153.25 J7.111 ; J7.61 56.95,153.15 56.4,152.6 56.4,150.8 v2(56.7,150.5)
MEMORY.RA11: length 176.4
  TOP w0.102: U1.P11 v1(43.9,133.2)
  TOP w0.2: U40.25 38.23,153.01 39.41,153.01 40.06,153.66 43.59,153.66 43.85,153.4 v2(43.85,152.8) 46.2,152.8 46.4,153 46.45,153 46.48,153.03 U41.25 49.15,153.01 51.11,153.01 51.75,153.66 55.3,153.66 55.55,153.4 58.21,153.4 58.59,153.03 U42.25 60.06,153.01 62.01,153.01 62.66,153.66 66.71,153.66 67.34,153.03 U43.25 70.97,153.01 72.96,153.01 73.6,153.66 76.55,153.66 77.17,153.03 U44.25 81.89,153.01 83.49,153.01 84.13,153.66 88.34,153.66 88.97,153.03 91.03,153.03 91.03,153.03 U45.25 92.8,153.01 94.62,153.01 95.26,153.66 97.96,153.66 98.3,154 99.65,154 100.62,153.03 U46.25 105.28,153.03 105.91,153.66 110.69,153.66 111.32,153.03 U47.25 ; v2(38.55,140.95) 43.05,140.95 v2(43.7,141.6)
  INNER1 w0.102: v1(43.9,133.2) 43.9,133.66 44.28,134.04 44.28,135.36 43.9,135.74 43.9,136.01
  INNER1 w0.2: 43.9,136.01 43.9,141.4 v2(43.7,141.6) 43.85,141.75 43.85,142.11 44.36,142.62 44.36,143.12 43.85,143.63 43.85,147.41 42.93,148.33 42.93,148.82 43.85,149.75 v2(43.85,152.8)
  INNER2 w0.2: v2(43.7,141.6) 44.05,141.25 49.6,141.25 50.4,142.05 53.85,142.05 54.05,141.85 55.44,141.85 55.63,142.05 56.8,142.05 57.77,141.08 v2(57.82,141.08) 57.95,140.95 72.6,140.95 v2(72.85,141.2) 73.7,140.35 75.95,140.35 76.65,141.05 86.65,141.05 v2(86.8,141.2)
  BOTTOM w0.2: J7.162 87.25,144.72 86.2,143.67 86.2,141.8 v2(86.8,141.2) ; J7.12 38.65,145.11 37.55,144.01 37.55,141.35 37.95,140.95 v2(38.55,140.95) ; J7.112 72.25,141.8 v2(72.85,141.2) ; v2(57.82,141.08) 56.65,142.25 56.65,144.3 57.25,144.9 J7.62
MEMORY.RA12: length 123.4
  TOP w0.102: U1.T9 v1(45.9,135.2)
  TOP w0.2: U47.4 105.99,158.11 105.36,157.49 100.71,157.49 100.09,158.11 U46.4 94.61,158.11 93.98,157.49 91.5,157.49 91.26,157.25 89,157.25 88.77,157.49 88.14,158.11 v2(87.55,158.11) U45.4 84.16,158.11 83.53,157.49 80.4,157.49 80.28,157.6 77,157.6 76.49,158.11 U44.4 73.24,158.11 v2(72.55,157.42) 72.48,157.49 69.77,157.49 68.9,158.35 65.35,158.35 65.11,158.11 U43.4 62.53,158.11 61.9,157.49 58.85,157.49 58.38,157.95 58.37,157.95 58.31,158 55.7,158 v2(55.39,158.31) 54.26,158.31 54.06,158.11 U42.4 51.42,158.11 50.79,157.49 46.81,157.49 v2(46.8,157.5) 45.95,157.5 44.95,158.5 43.5,158.5 43.11,158.11 U41.4 40.31,158.11 39.69,157.49 36.56,157.49 v2(36.55,157.5) 34.57,157.5 33.96,158.11 U40.4
  INNER1 w0.102: v1(45.9,135.2) 45.9,135.83 46.08,136.01
  INNER1 w0.2: v2(46.8,157.5) 45.65,156.35 45.65,151.65 47.6,149.7 47.6,141.3 46.08,139.78 46.08,136.01
  BOTTOM w0.2: J7.163 87.55,155.55 87.95,155.95 87.95,156.45 87.55,156.85 v2(87.55,158.11) ; J7.13 38.95,157.15 38.65,157.45 36.6,157.45 v2(36.55,157.5) ; J7.63 57.55,155.39 57.27,155.68 57.17,155.68 56.35,156.5 56.35,157.3 55.5,158.15 55.5,158.2 55.45,158.25 55.45,158.25 v2(55.39,158.31) ; J7.113 v2(72.55,157.42)
MEMORY.RA13: length 178.1
  TOP w0.102: U1.T8 v1(47.9,135.2)
  TOP w0.2: U40.28 38.23,156.82 39.62,156.82 40.28,157.49 43.19,157.49 43.65,157.95 44.85,157.95 45.95,156.85 v2(47.35,156.85) 47.36,156.84 U41.28 49.15,156.82 50.74,156.82 51.41,157.49 54.1,157.49 54.52,157.9 54.95,157.9 55.1,157.75 55.12,157.75 55.27,157.6 58.15,157.6 58.91,156.84 U42.28 60.06,156.82 61.37,156.82 61.81,156.82 62.45,157.47 68.99,157.47 69.61,156.84 U43.28 71,156.8 72.85,156.8 73.52,157.47 76.44,157.47 77.65,156.25 80.05,156.25 80.64,156.84 U44.28 81.89,156.82 83.49,156.82 84.15,157.49 88.16,157.49 88.8,156.85 92.77,156.85 U45.28 92.8,156.82 93.96,156.82 94.61,157.47 100.09,157.47 100.71,156.84 U46.28 105.34,156.84 105.97,157.47 110.79,157.47 111.41,156.84 U47.28
  INNER1 w0.102: v1(47.9,135.2) 47.9,135.76 48.16,136.01
  INNER1 w0.2: 48.16,136.01 49.2,137.06 49.2,141.7 v2(49.4,141.9) 49.2,142.1 49.2,151 47.6,152.6 47.3,152.6 46.6,153.3 46.6,154.25 47.1,154.75 47.75,154.75 48.05,155.05 48.05,156.1 47.78,156.37 47.78,156.42 v2(47.35,156.85)
  INNER2 w0.2: v2(38.15,141.65) 38.35,141.85 38.35,141.9 38.7,142.25 40.2,142.25 41.4,141.05 42.45,141.05 43.1,141.7 43.1,141.85 43.5,142.25 44.65,142.25 45.25,141.65 49.15,141.65 v2(49.4,141.9) 49.95,142.45 54.02,142.45 54.22,142.25 55.27,142.25 55.47,142.45 57.3,142.45 57.42,142.33 57.7,142.05 v2(57.85,141.9) 58.4,141.35 72.1,141.35 72.8,142.05 v2(72.85,142.05) 74.15,140.75 75.75,140.75 76.45,141.45 86.2,141.45 v2(86.8,142.05)
  BOTTOM w0.2: v2(72.85,142.05) J7.114 ; J7.64 57.85,144.9 57.05,144.1 57.05,142.7 v2(57.85,141.9) ; v2(86.8,142.05) 86.8,143.7 87.85,144.75 J7.164 ; v2(38.15,141.65) 38.15,144.01 39.25,145.11 J7.14
MEMORY.RA14: length 128.8
  TOP w0.102: U1.T7 v1(48.9,135.2)
  TOP w0.2: U47.3 105.99,159.38 105.36,158.75 100.7,158.75 100.07,159.38 U46.3 94.58,159.38 93.96,158.75 90.2,158.75 90.05,158.9 88.6,158.9 v2(88.15,159.35) 85.71,159.35 U45.3 84.16,159.38 83.53,158.75 78.27,158.75 77.64,159.38 U44.3 72.88,159.38 v2(72.85,159.35) 72.25,158.75 69.8,158.75 69.17,159.38 U43.3 61.83,159.38 61.2,158.75 58.69,158.75 58.65,158.8 56.6,158.8 v2(56.2,159.2) 56.02,159.38 U42.3 51.42,159.38 50.79,158.75 v2(47.4,158.75) 46.5,158.75 45.87,159.38 U41.3 40.08,159.38 v2(39.92,159.23) 39.45,158.75 34.61,158.75 33.98,159.38 U40.3
  INNER1 w0.102: 48.9,136.01 v1(48.9,135.2)
  INNER1 w0.2: 48.9,136.01 48.9,136.19 49.6,136.89 49.6,141.25 50,141.65 50,142.25 49.6,142.65 49.6,151.25 47.75,153.1 47.4,153.1 47.02,153.48 47.02,154.03 47.3,154.3 48.05,154.3 48.48,154.73 48.48,157.67 v2(47.4,158.75)
  BOTTOM w0.2: v2(39.92,159.23) 39.92,157.53 39.55,157.15 J7.15 ; v2(88.15,159.35) 88.35,159.15 88.35,155.75 88.15,155.55 J7.165 ; v2(56.2,159.2) 56.8,158.6 56.8,156.65 57.38,156.07 57.43,156.07 57.76,155.75 57.95,155.75 58.15,155.55 J7.65 ; v2(72.85,159.35) 73.15,159.05 J7.115
MEMORY.RA15: length 191
  TOP w0.102: U1.T6 v1(49.9,135.2)
  TOP w0.2: U40.31 38.23,160.63 39.83,160.63 40.47,161.28 44.88,161.28 45.51,160.65 U41.31 49.15,160.63 50.74,160.63 51.41,161.3 54.1,161.3 54.1,161.3 v2(55.45,161.3) 56.25,161.3 56.9,160.65 U42.31 60.06,160.63 61.66,160.63 62.3,161.28 66.71,161.28 67.34,160.65 U43.31 70.97,160.63 72.08,160.63 72.75,161.3 76.56,161.3 76.6,161.25 77.65,161.25 78.25,160.65 U44.31 81.89,160.63 83.49,160.63 84.13,161.28 86.82,161.28 86.85,161.3 v2(87.55,161.3) 88.52,161.3 89.17,160.65 U45.31 92.8,160.63 94.4,160.63 95.04,161.28 99.46,161.28 100.08,160.65 U46.31 105.05,160.65 105.68,161.28 110.73,161.28 111.35,160.65 U47.31
  INNER1 w0.102: 50.42,136.01 49.9,135.49 v1(49.9,135.2)
  INNER1 w0.2: v2(55.45,161.3) 55.45,159.65 51.35,155.55 51.35,140.9 51.55,140.7 51.55,140.2 v2(50.65,139.3) 50.65,136.24 50.42,136.01 ; v2(88.3,142.85) 88.3,147.05 87.75,147.6 87.75,150.55 88.15,150.95 88.15,158.5 87.2,159.45 87.2,160.95 v2(87.55,161.3)
  INNER2 w0.2: v2(88.3,142.85) 87.68,143.47 80.72,143.47 79.9,142.65 74.35,142.65 v2(73.75,142.05) 73.15,142.65 70.25,142.65 69.4,143.5 60.3,143.5 v2(58.75,141.95) ; v2(50.65,139.3) 49.45,140.5 41.35,140.5 40.2,141.65 v2(38.95,141.65)
  BOTTOM w0.2: J7.166 88.45,143 v2(88.3,142.85) ; J7.16 39.85,144.9 38.95,144 v2(38.95,141.65) ; v2(58.75,141.95) 58.2,142.5 57.85,142.5 57.45,142.9 57.45,143.9 58.45,144.9 J7.66 ; J7.116 73.45,142.35 v2(73.75,142.05)
MEMORY.RA16: length 106.4
  TOP w0.2: U40.2 33.96,160.65 34.59,160.03 v2(39.88,160.03) 40.5,160.65 U41.2 44.88,160.65 45.5,160.03 50.79,160.03 51.42,160.65 U42.2 54.7,160.65 55.33,160.03 v2(56.42,160.03) 61.7,160.03 62.33,160.65 U43.2 66.71,160.65 67.36,160 67.9,160 67.91,160 72.41,160 v2(73.05,160.65) U44.2 77.62,160.65 78.25,160.03 83.53,160.03 84.16,160.65 U45.2 v2(88.15,160.65) 88.53,160.65 88.98,160.2 90.6,160.2 90.77,160.03 94.45,160.03 95.07,160.65 U46.2 99.45,160.65 100.07,160.03 105.38,160.03 106,160.65 U47.2
  BOTTOM w0.2: J7.167 88.75,160.05 v2(88.15,160.65) ; J7.67 58.75,156 58.4,156.35 57.72,156.35 57.6,156.48 57.57,156.48 57.2,156.85 57.2,159.24 v2(56.42,160.03) ; J7.17 40.15,157.05 40.55,157.45 40.55,159.5 40.02,160.03 v2(39.88,160.03) ; v2(73.05,160.65) 73.75,159.95 J7.117
MEMORY.RD0: length 310.7
  TOP w0.102: U1.R15 v1(39.9,134.2)
  TOP w0.2: v2(122.27,149.02) 119.31,146.06 111.26,146.06 110.63,146.68 U47.13 105.99,146.68 105.36,146.06 100.09,146.06 99.47,146.68 U46.13 95.43,146.68 94.81,146.06 90.4,146.06 88.55,147.9 v2(88.35,147.9) 88.05,147.9 86.83,146.68 U45.13 84.16,146.68 83.53,146.06 78.09,146.06 77.47,146.68 U44.13 73.24,146.68 72.62,146.06 67.35,146.06 66.73,146.68 U43.13 63.67,146.5 62.35,146.5 61.91,146.06 56.44,146.06 55.81,146.68 U42.13 51.58,146.68 50.95,146.06 45.52,146.06 44.9,146.68 U41.13 40.13,146.68 39.5,146.05 33.3,146.05 32.67,146.68 U40.13 v2(29.12,146.68)
  INNER1 w0.102: v1(39.9,134.2) 39.35,134.75 39.35,136.01
  INNER1 w0.2: v2(88.35,147.9) 89,147.25 89,142.6 88.65,142.25 87.85,142.25 87.4,142.7 77.65,142.7 76.9,141.95 v2(74.6,141.95) 74.6,142.05 74,142.65 72.3,142.65 71.05,141.4 60.25,141.4 v2(59.65,142) ; 39.35,136.01 39.35,136.85 38.35,137.85 33,137.85 29.7,141.15 29.7,146.1 v2(29.12,146.68) 29.12,149.37 32.25,152.5 32.25,157.3 35.95,161 53,161 55,163 55,164.05
  INNER1 w0.4: 55,164.05 55,207.2 ; 51.6,213.06 54.34,213.06 54.35,213.05 56.55,213.05 57.6,214.1 82.9,214.1 83.94,213.06 93.1,213.06
  INNER2 w0.4: 55,207.2 55,213.05
  BOTTOM w0.1: v1(39.9,134.2) 39.58,134.52 39.58,136.01
  BOTTOM w0.2: J7.168 89.05,147.2 v2(88.35,147.9) ; v2(59.65,142) 58.75,142.9 58.25,142.9 57.9,143.25 57.9,143.75 59.05,144.9 J7.68 ; J7.118 74.05,142.6 74.6,142.05 v2(74.6,141.95) ; J7.18 40.45,144.94 39.58,144.07 39.58,136.01
MEMORY.RD1: length 324.4
  TOP w0.102: U1.R16 v1(38.9,134.2)
  TOP w0.2: v2(29.1,145.4) 29.11,145.41 U40.14 32.64,145.41 33.27,144.78 39.48,144.78 40.11,145.41 U41.14 44.92,145.41 45.54,144.78 50.88,144.78 51.51,145.41 U42.14 55.72,145.41 56.34,144.78 62.03,144.78 62.66,145.41 U43.14 66.75,145.41 67.37,144.78 72.62,144.78 73.24,145.41 U44.14 77.29,145.41 77.91,144.78 83.88,144.78 84.51,145.41 U45.14 88.57,145.41 89.2,144.78 94.73,144.78 95.36,145.41 U46.14 99.49,145.41 100.11,144.78 v2(102.15,144.78) 105.36,144.78 105.99,145.41 U47.14 110.66,145.41 111.3,144.76 120.15,144.76 v2(122.41,147.02)
  INNER1 w0.102: v1(38.9,134.2) 38.52,134.58 38.52,135.98 38.55,136.01
  INNER1 w0.2: 59.9,164.05 59.9,163.35 63.2,160.05 v2(66.1,160.05) ; 38.55,136.01 38.55,137.05 38.15,137.45 32.75,137.45 29.1,141.1 v2(29.1,145.4)
  INNER1 w0.4: 61.1,213.06 57.86,213.06 56.82,212.02 29.48,212.02 28.44,213.06 19.6,213.06 ; 59.9,164.05 59.9,207.2
  INNER2 w0.2: v2(90.1,159.5) 88.95,159.5 88.45,160 87.7,160 87.3,160.4 80.1,160.4 79.2,161.3 v2(78.55,161.3) 78.12,160.88 74.32,160.88 73.5,160.05 v2(66.1,160.05) 57.6,160.05 56.8,159.25 56.8,152.55 57,152.35 v2(57,151.75) 53.75,151.75 53.15,151.15 49.3,151.15 48.65,151.8 40.95,151.8 v2(40.4,152.35)
  INNER2 w0.4: 61.1,213.06 59.9,211.86 59.9,207.2
  BOTTOM w0.2: J7.19 40.75,152.7 v2(40.4,152.35) ; v2(78.55,161.3) 76.9,161.3 74.35,158.75 J7.119 ; v2(102.15,144.78) 102.15,146.38 99.45,149.08 99.45,151.15 100.15,151.85 100.15,157.8 98.45,159.5 91.13,159.5 v2(90.1,159.5) 89.2,158.6 89.2,156.9 89.35,156.75 J7.169 ; v2(57,151.75) 57,152.55 57.4,152.95 59.15,152.95 59.35,153.15 J7.69
MEMORY.RD2: length 242.9
  TOP w0.102: U1.R14 v1(40.9,134.2)
  TOP w0.2: U40.15 34.76,144.14 v2(35.35,143.55) 35.4,143.5 39.86,143.5 v2(40.18,143.82) 40.5,144.14 U41.15 44.89,144.14 45.52,143.51 50.79,143.51 51.42,144.14 U42.15 55.8,144.14 56.45,143.5 v2(58.55,143.5) 62.05,143.5 62.69,144.14 U43.15 66.72,144.14 67.36,143.5 72.55,143.5 73.19,144.14 U44.15 75.96,144.14 76.7,143.4 v2(76.9,143.4) 77.9,143.4 78,143.5 83.9,143.5 84.54,144.14 U45.15 88.55,144.14 89.19,143.5 v2(89.65,143.5) 94.7,143.5 95.34,144.14 U46.15 99.46,144.14 100.09,143.51 105.36,143.51 105.99,144.14 U47.15 110.63,144.14 111.25,143.51 121.12,143.51 v2(122.62,145.02)
  INNER1 w0.102: 40.4,136.01 40.4,134.7 v1(40.9,134.2)
  INNER1 w0.2: v2(35.35,143.55) 35.35,139.3 36.4,138.25 38.55,138.25 40.4,136.4 40.4,136.01 ; v2(58.55,143.5) 59.15,143.5 59.17,143.52 62,143.52 62.7,144.22 62.7,159.8 59.2,163.3 59.2,164.05
  INNER1 w0.4: 19.6,215.6 28.6,215.6 29.64,214.56 56.71,214.56 57.75,215.6 61.1,215.6 ; 59.2,207.2 59.2,164.05
  INNER2 w0.4: 59.2,207.2 59.2,213.7 61.1,215.6
  BOTTOM w0.2: v2(40.18,143.82) 41.05,144.69 J7.20 ; v2(76.9,143.4) 75.85,143.4 74.65,144.6 J7.120 ; J7.70 59.65,144.6 v2(58.55,143.5) ; J7.170 v2(89.65,143.5)
MEMORY.RD3: length 316.6
  TOP w0.1: U1.T15 39.9,135.2
  TOP w0.102: 39.9,135.2 39.9,136.01
  TOP w0.2: v2(122.95,144.02) 121.8,142.87 U47.17 111.33,142.87 110.71,143.5 105.91,143.5 105.28,142.87 U46.17 101.52,142.87 v2(101.5,142.85) 100.1,142.85 99.46,143.5 95.4,143.5 94.75,142.85 92.8,142.85 U45.17 90.96,142.87 90.94,142.85 89.19,142.85 88.54,143.5 84.5,143.5 83.85,142.85 81.89,142.85 U44.17 81.8,142.8 76.65,142.8 75.95,143.5 73.39,143.5 72.75,142.85 70.97,142.85 U43.17 70.94,142.85 67.36,142.85 66.71,143.5 62.7,143.5 62.05,142.85 60.06,142.85 U42.17 56.33,142.87 55.7,143.5 51.45,143.5 50.85,142.9 49.16,142.9 U41.17 46.13,142.87 46.1,142.9 45.6,142.9 45.57,142.87 45.51,142.87 44.88,143.5 40.71,143.5 40.06,142.85 38.23,142.85 U40.17 38.2,142.86 37.75,142.86 37.55,142.66 37.55,139.1 39.9,136.75 39.9,136.01
  INNER1 w0.2: v2(57.65,152.35) 59.75,154.45 59.75,161.4 57.8,163.35 57.8,164.05
  INNER1 w0.4: 19.6,218.14 28.46,218.14 29.5,217.1 56.45,217.1 57.49,218.14 61.1,218.14 ; 57.8,164.05 57.8,207.2
  INNER2 w0.2: v2(89.85,158.25) 89.7,158.4 88.25,158.4 86.65,160 79.52,160 79.07,160.45 76.9,160.45 v2(76.45,160) 74.45,160 73.14,158.69 72.5,158.69 71.87,159.32 65.83,159.32 65.55,159.6 58.9,159.6 57.2,157.9 57.2,152.8 v2(57.65,152.35) 57.65,151.55 57.25,151.15 55.7,151.15 54.4,149.85 v2(40.35,149.85)
  INNER2 w0.4: 61.1,218.14 60.06,218.14 57.8,215.88 57.8,207.2
  BOTTOM w0.2: J7.21 41.35,150.85 v2(40.35,149.85) ; J7.71 59.95,153.1 59.35,152.5 57.8,152.5 v2(57.65,152.35) ; J7.171 89.95,158.15 v2(89.85,158.25) 89.85,158.35 90.6,159.1 90.97,159.1 90.97,159.1 98.28,159.1 99.65,157.73 99.65,151.92 99.05,151.31 99.05,148.92 101.5,146.47 v2(101.5,142.85) ; J7.121 74.95,158.5 v2(76.45,160)
